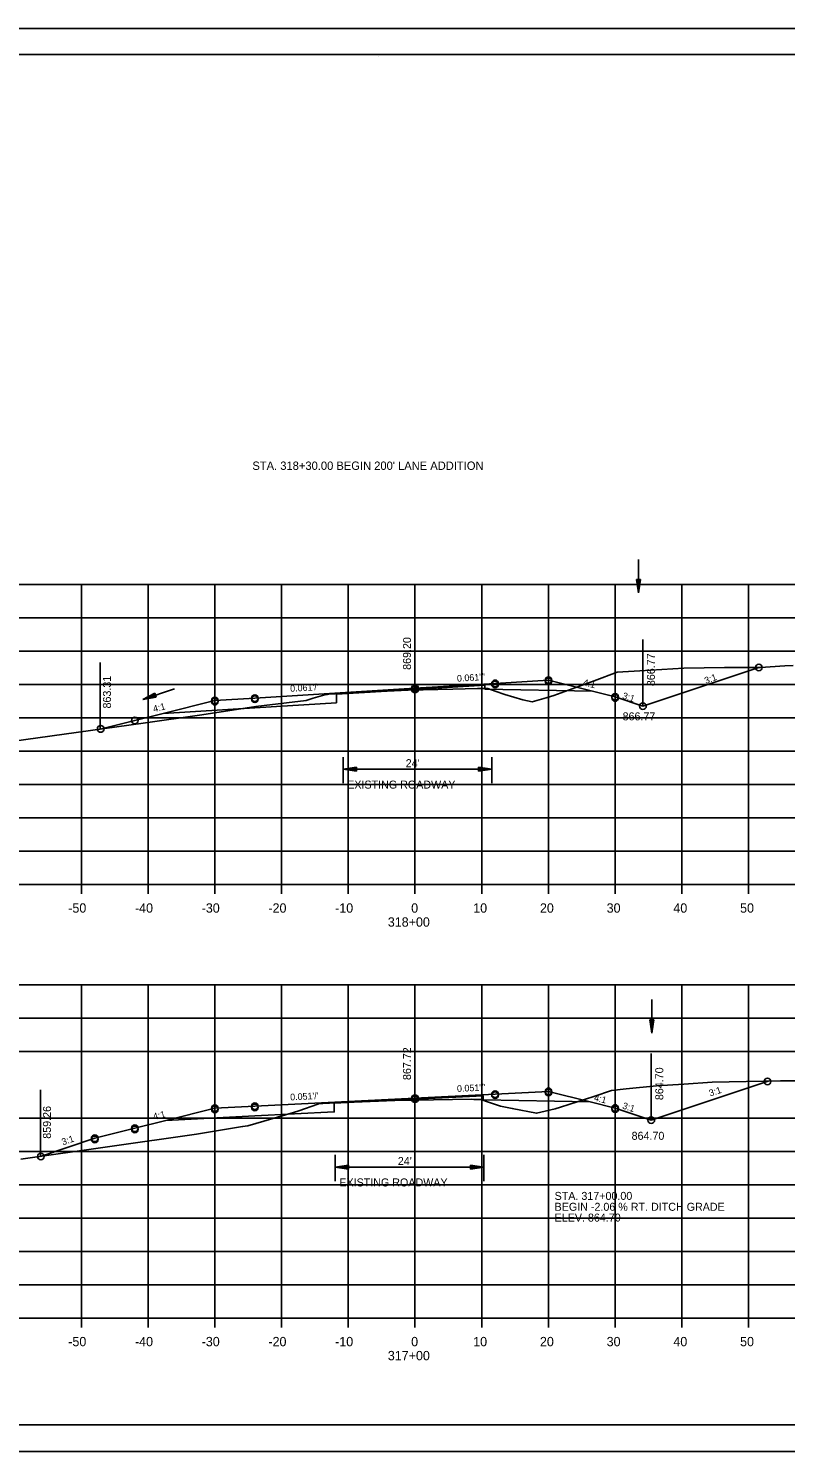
# Model space of a CAD drawing. Extents: x 1486524 to 1499135, y 326561 to 337924.
# Drawn here: x 1488925 to 1489038.4, y 335979.4 to 336192.7 of the extents above; entities that cross this region are included whole.
import ezdxf

# ---------------------------------------------------------------- set-up
doc = ezdxf.new("R2010")
doc.units = 0
for name, color, linetype in [('Default', 7, 'Continuous'), ('E_Const Align', 7, 'Continuous'), ('E_Const Align Station', 7, 'Continuous'), ('E_Ownership Information', 7, 'Continuous'), ('E_Property Line', 7, 'Continuous'), ('E_Proposed ROW and Easements', 7, 'Continuous'), ('E_Proposed ROW Fig Annot', 7, 'Continuous'), ('E_Quarter Calls', 7, 'Continuous'), ('E_Survey Point', 7, 'Continuous'), ('E_Title Sheet', 7, 'Continuous'), ('E_Tract Number', 7, 'Continuous'), ('R_Water Annot', 7, 'Continuous'), ('R_Xsect Elev', 7, 'Continuous'), ('R_Xsect Slope', 7, 'Continuous')]:
    doc.layers.add(name, color=color, linetype=linetype)

msp = doc.modelspace()

# ---------------------------------------------------------------- linework, layer by layer
at = {"layer": 'E_Const Align'}
for p, q in [((1488842.89, 336064.36), (1489122.89, 336064.36)), ((1488932.89, 336062.96), (1488932.89, 336064.36)), ((1488942.89, 336062.96), (1488942.89, 336064.36)), ((1488952.89, 336062.96), (1488952.89, 336064.36)), ((1488962.89, 336062.96), (1488962.89, 336064.36)), ((1488972.89, 336062.96), (1488972.89, 336064.36)), ((1488982.89, 336062.96), (1488982.89, 336064.36)), ((1488992.89, 336062.96), (1488992.89, 336064.36)), ((1489002.89, 336062.96), (1489002.89, 336064.36)), ((1489012.89, 336062.96), (1489012.89, 336064.36)), ((1489022.89, 336062.96), (1489022.89, 336064.36)), ((1489032.89, 336062.96), (1489032.89, 336064.36)), ((1488842.89, 335999.36), (1489122.89, 335999.36)), ((1488932.89, 335997.96), (1488932.89, 335999.36)), ((1488942.89, 335997.96), (1488942.89, 335999.36)), ((1488952.89, 335997.96), (1488952.89, 335999.36)), ((1488962.89, 335997.96), (1488962.89, 335999.36)), ((1488972.89, 335997.96), (1488972.89, 335999.36)), ((1488982.89, 335997.96), (1488982.89, 335999.36)), ((1488992.89, 335997.96), (1488992.89, 335999.36)), ((1489002.89, 335997.96), (1489002.89, 335999.36)), ((1489012.89, 335997.96), (1489012.89, 335999.36)), ((1489022.89, 335997.96), (1489022.89, 335999.36)), ((1489032.89, 335997.96), (1489032.89, 335999.36))]:
    msp.add_line(p, q, dxfattribs=at)
at = {"layer": 'E_Ownership Information'}
for p, q in [((1488842.89, 336109.36), (1489122.89, 336109.36)), ((1488932.89, 336064.36), (1488932.89, 336109.36)), ((1488942.89, 336064.36), (1488942.89, 336109.36)), ((1488952.89, 336064.36), (1488952.89, 336109.36)), ((1488962.89, 336064.36), (1488962.89, 336109.36)), ((1488972.89, 336064.36), (1488972.89, 336109.36)), ((1488982.89, 336064.36), (1488982.89, 336109.36)), ((1488992.89, 336064.36), (1488992.89, 336109.36)), ((1489002.89, 336064.36), (1489002.89, 336109.36)), ((1489012.89, 336064.36), (1489012.89, 336109.36)), ((1489022.89, 336064.36), (1489022.89, 336109.36)), ((1489032.89, 336064.36), (1489032.89, 336109.36)), ((1488842.89, 336104.36), (1489122.89, 336104.36)), ((1488842.89, 336099.36), (1489122.89, 336099.36)), ((1488842.89, 336094.36), (1489122.89, 336094.36)), ((1488842.89, 336089.36), (1489122.89, 336089.36)), ((1488842.89, 336084.36), (1489122.89, 336084.36)), ((1488842.89, 336079.36), (1489122.89, 336079.36)), ((1488842.89, 336074.36), (1489122.89, 336074.36)), ((1488842.89, 336069.36), (1489122.89, 336069.36)), ((1488842.89, 336064.36), (1489122.89, 336064.36)), ((1488842.89, 336049.36), (1489122.89, 336049.36)), ((1488932.89, 335999.36), (1488932.89, 336049.36)), ((1488942.89, 335999.36), (1488942.89, 336049.36)), ((1488952.89, 335999.36), (1488952.89, 336049.36)), ((1488962.89, 335999.36), (1488962.89, 336049.36)), ((1488972.89, 335999.36), (1488972.89, 336049.36)), ((1488982.89, 335999.36), (1488982.89, 336049.36)), ((1488992.89, 335999.36), (1488992.89, 336049.36)), ((1489002.89, 335999.36), (1489002.89, 336049.36)), ((1489012.89, 335999.36), (1489012.89, 336049.36)), ((1489022.89, 335999.36), (1489022.89, 336049.36)), ((1489032.89, 335999.36), (1489032.89, 336049.36)), ((1488842.89, 336044.36), (1489122.89, 336044.36)), ((1488842.89, 336039.36), (1489122.89, 336039.36)), ((1488842.89, 336029.36), (1489122.89, 336029.36)), ((1488842.89, 336024.36), (1489122.89, 336024.36)), ((1488842.89, 336019.36), (1489122.89, 336019.36)), ((1488842.89, 336014.36), (1489122.89, 336014.36)), ((1488842.89, 336009.36), (1489122.89, 336009.36)), ((1488842.89, 336004.36), (1489122.89, 336004.36)), ((1488842.89, 335999.36), (1489122.89, 335999.36))]:
    msp.add_line(p, q, dxfattribs=at)
at = {"layer": 'E_Property Line'}
for p, q in [((1488824.89, 336188.82), (1489141.07, 336188.82)), ((1488977.41, 336188.56), (1488977.41, 336188.56)), ((1488977.41, 336188.56), (1488977.41, 336188.56)), ((1489141.07, 335983.36), (1488824.89, 335983.36))]:
    msp.add_line(p, q, dxfattribs=at)
at = {"layer": 'E_Proposed ROW and Easements'}
for p, q in [((1488972.12, 336083.48), (1488972.12, 336079.55)), ((1488994.39, 336083.48), (1488994.39, 336079.55)), ((1488974.12, 336081.96), (1488972.12, 336081.66)), ((1488974.12, 336081.36), (1488972.12, 336081.66)), ((1488974.12, 336081.91), (1488972.45, 336081.66)), ((1488974.12, 336081.41), (1488972.45, 336081.66)), ((1488974.12, 336081.86), (1488972.79, 336081.66)), ((1488974.12, 336081.46), (1488972.79, 336081.66)), ((1488974.12, 336081.81), (1488973.13, 336081.66)), ((1488974.12, 336081.51), (1488973.13, 336081.66)), ((1488974.12, 336081.76), (1488973.47, 336081.66)), ((1488974.12, 336081.56), (1488973.47, 336081.66)), ((1488974.12, 336081.71), (1488973.8, 336081.66)), ((1488974.12, 336081.61), (1488973.8, 336081.66)), ((1488974.12, 336081.36), (1488974.12, 336081.96)), ((1488992.39, 336081.96), (1488994.39, 336081.66)), ((1488992.39, 336081.96), (1488992.39, 336081.36)), ((1488992.39, 336081.91), (1488994.06, 336081.66)), ((1488992.39, 336081.86), (1488993.71, 336081.66)), ((1488992.39, 336081.81), (1488993.38, 336081.66)), ((1488992.39, 336081.76), (1488993.04, 336081.66)), ((1488992.39, 336081.71), (1488992.71, 336081.66)), ((1488992.39, 336081.36), (1488994.39, 336081.66)), ((1488992.39, 336081.57), (1488993.04, 336081.66)), ((1488992.39, 336081.47), (1488993.71, 336081.66)), ((1488992.39, 336081.41), (1488994.06, 336081.66)), ((1488992.39, 336081.52), (1488993.38, 336081.66)), ((1488992.39, 336081.62), (1488992.71, 336081.66)), ((1488970.93, 336023.84), (1488970.93, 336019.91)), ((1488993.21, 336023.84), (1488993.21, 336019.91)), ((1488972.93, 336022.32), (1488970.93, 336022.02)), ((1488972.93, 336021.72), (1488970.93, 336022.02)), ((1488972.93, 336022.27), (1488971.27, 336022.02)), ((1488972.93, 336021.77), (1488971.27, 336022.02)), ((1488972.93, 336022.22), (1488971.61, 336022.02)), ((1488972.93, 336021.82), (1488971.61, 336022.02)), ((1488972.93, 336022.17), (1488971.95, 336022.02)), ((1488972.93, 336021.87), (1488971.95, 336022.02)), ((1488972.93, 336022.12), (1488972.28, 336022.02)), ((1488972.93, 336021.92), (1488972.28, 336022.02)), ((1488972.93, 336022.07), (1488972.62, 336022.02)), ((1488972.93, 336021.97), (1488972.62, 336022.02)), ((1488972.93, 336021.72), (1488972.93, 336022.32)), ((1488991.21, 336022.33), (1488993.21, 336022.03)), ((1488991.21, 336022.33), (1488991.21, 336021.73)), ((1488991.21, 336022.28), (1488992.88, 336022.03)), ((1488991.21, 336022.22), (1488992.53, 336022.03)), ((1488991.21, 336022.17), (1488992.2, 336022.03)), ((1488991.21, 336022.12), (1488991.86, 336022.03)), ((1488991.21, 336022.07), (1488991.53, 336022.03)), ((1488991.21, 336021.73), (1488993.21, 336022.03)), ((1488991.21, 336021.93), (1488991.86, 336022.03)), ((1488991.21, 336021.83), (1488992.53, 336022.03)), ((1488991.21, 336021.78), (1488992.88, 336022.03)), ((1488991.21, 336021.88), (1488992.2, 336022.03)), ((1488991.21, 336021.98), (1488991.53, 336022.03))]:
    msp.add_line(p, q, dxfattribs=at)
at = {"layer": 'E_Proposed ROW Fig Annot'}
for p, q in [((1489016.1, 336110.12), (1489016.4, 336108.12)), ((1489016.7, 336110.12), (1489016.1, 336110.12)), ((1489016.15, 336110.12), (1489016.4, 336108.46)), ((1489016.2, 336110.12), (1489016.4, 336108.8)), ((1489016.25, 336110.12), (1489016.4, 336109.13)), ((1489016.3, 336110.12), (1489016.4, 336109.47)), ((1489016.35, 336110.12), (1489016.4, 336109.81)), ((1489016.7, 336110.12), (1489016.4, 336108.12)), ((1489016.5, 336110.12), (1489016.4, 336109.47)), ((1489016.6, 336110.12), (1489016.4, 336108.8)), ((1489016.65, 336110.12), (1489016.4, 336108.46)), ((1489016.55, 336110.12), (1489016.4, 336109.13)), ((1489016.45, 336110.12), (1489016.4, 336109.81)), ((1488943.9, 336093.05), (1488942.1, 336092.12)), ((1488943.91, 336093), (1488942.41, 336092.23)), ((1488944.09, 336092.48), (1488943.9, 336093.05)), ((1488944.09, 336092.48), (1488942.1, 336092.12)), ((1488944.07, 336092.53), (1488942.41, 336092.23)), ((1488943.93, 336092.95), (1488942.74, 336092.34)), ((1488944.06, 336092.58), (1488942.74, 336092.34)), ((1488943.95, 336092.91), (1488943.06, 336092.45)), ((1488944.04, 336092.62), (1488943.06, 336092.45)), ((1488943.96, 336092.86), (1488943.38, 336092.56)), ((1488944.02, 336092.67), (1488943.38, 336092.56)), ((1488943.98, 336092.81), (1488943.69, 336092.66)), ((1488944.01, 336092.72), (1488943.69, 336092.66)), ((1488972.12, 336081.66), (1488994.39, 336081.66)), ((1489018.09, 336044.12), (1489018.39, 336042.12)), ((1489018.69, 336044.12), (1489018.09, 336044.12)), ((1489018.14, 336044.12), (1489018.39, 336042.45)), ((1489018.19, 336044.12), (1489018.39, 336042.8)), ((1489018.24, 336044.12), (1489018.39, 336043.13)), ((1489018.29, 336044.12), (1489018.39, 336043.47)), ((1489018.34, 336044.12), (1489018.39, 336043.8)), ((1489018.69, 336044.12), (1489018.39, 336042.12)), ((1489018.49, 336044.12), (1489018.39, 336043.47)), ((1489018.59, 336044.12), (1489018.39, 336042.8)), ((1489018.64, 336044.12), (1489018.39, 336042.45)), ((1489018.54, 336044.12), (1489018.39, 336043.13)), ((1489018.44, 336044.12), (1489018.39, 336043.8)), ((1488970.93, 336022.02), (1488993.21, 336022.03))]:
    msp.add_line(p, q, dxfattribs=at)
at = {"layer": 'E_Quarter Calls'}
for p, q in [((1488812.48, 336192.71), (1489145.82, 336192.71)), ((1488812.48, 335979.38), (1489145.82, 335979.38))]:
    msp.add_line(p, q, dxfattribs=at)
for points in [[(1488812.48, 336192.71), (1489145.82, 336192.71), (1489145.82, 335979.38), (1488812.48, 335979.38)], [(1489058.81, 336188.82), (1489058.81, 336178.94), (1489094.54, 336178.94), (1489094.54, 336176.02), (1489117.74, 336176.02), (1489117.74, 336151.69), (1489141.07, 336151.69), (1489141.07, 335983.36), (1488824.89, 335983.36), (1488824.89, 336188.82)]]:
    msp.add_lwpolyline(points, close=True, dxfattribs=at)
for centre in [(1489034.44, 336096.92), (1489034.44, 336096.92), (1489002.89, 336095.02), (1489002.89, 336095.02), (1489002.89, 336094.85), (1488982.89, 336093.8), (1488982.89, 336093.8), (1488982.89, 336093.63), (1488994.89, 336094.53), (1488994.89, 336094.53), (1488994.89, 336094.36), (1489012.89, 336092.52), (1489012.89, 336092.52), (1488952.89, 336091.97), (1488952.89, 336091.97), (1488952.89, 336091.8), (1488958.89, 336092.33), (1488958.89, 336092.33), (1488958.89, 336092.16), (1489012.89, 336092.35), (1489017.06, 336091.12), (1489017.06, 336091.12), (1488940.89, 336088.97), (1488940.89, 336088.97), (1488935.78, 336087.7), (1489035.72, 336034.86), (1488994.89, 336032.96), (1488994.89, 336032.96), (1488994.89, 336032.79), (1489002.89, 336033.37), (1489002.89, 336033.37), (1489002.89, 336033.2), (1488952.89, 336030.84), (1488952.89, 336030.84), (1488952.89, 336030.67), (1488958.89, 336031.14), (1488958.89, 336031.14), (1488958.89, 336030.97), (1488982.89, 336032.36), (1488982.89, 336032.36), (1488982.89, 336032.19), (1489012.89, 336030.87), (1489012.89, 336030.87), (1489012.89, 336030.7), (1489018.31, 336029.06), (1488934.89, 336026.34), (1488934.89, 336026.34), (1488940.89, 336027.84), (1488940.89, 336027.84), (1488940.89, 336027.67), (1488934.89, 336026.17), (1488926.82, 336023.6)]:
    msp.add_circle(centre, 0.5, dxfattribs=at)
at = {"layer": 'E_Survey Point'}
for points in [[(1488945.16, 336090.04), (1488958.89, 336090.87), (1488971.11, 336091.62), (1488971.11, 336092.91), (1488982.89, 336093.63), (1488993.36, 336094.27), (1488993.37, 336093.69), (1489009.5, 336093.36)], [(1488945.56, 336029.01), (1488958.89, 336029.68), (1488970.78, 336030.29), (1488970.78, 336031.58), (1488982.89, 336032.19), (1488993.09, 336032.71), (1488993.1, 336032.12), (1489009.15, 336031.8)]]:
    msp.add_lwpolyline(points, dxfattribs=at)
at = {"layer": 'E_Title Sheet'}
for points in [[(1488935.71, 336087.67), (1488940.89, 336088.97), (1488945.16, 336090.04), (1488952.89, 336091.97), (1488958.89, 336092.33), (1488982.89, 336093.8), (1488994.89, 336094.53), (1489002.89, 336095.02), (1489009.5, 336093.36), (1489012.89, 336092.52), (1489017.06, 336091.12), (1489034.44, 336096.92)], [(1488926.74, 336023.62), (1488934.89, 336026.34), (1488940.89, 336027.84), (1488945.56, 336029.01), (1488952.89, 336030.84), (1488958.89, 336031.14), (1488982.89, 336032.36), (1488994.89, 336032.96), (1489002.89, 336033.37), (1489009.15, 336031.8), (1489012.89, 336030.87), (1489018.31, 336029.06), (1489035.82, 336034.89)]]:
    msp.add_lwpolyline(points, dxfattribs=at)
at = {"layer": 'E_Tract Number'}
for points in [[(1488922.43, 336085.81), (1488942.17, 336088.58), (1488950.59, 336089.76), (1488951.6, 336089.92), (1488959.05, 336091.09), (1488963.63, 336091.62), (1488966.56, 336091.95), (1488967.65, 336092.3), (1488969.37, 336092.83), (1488969.77, 336092.88), (1488969.98, 336092.9), (1488977.65, 336093.33), (1488981.89, 336093.54), (1488988.56, 336093.68), (1488992.24, 336093.77), (1488993.26, 336093.77), (1488993.83, 336093.76), (1488994.91, 336093.37), (1488996.35, 336092.88), (1488999.08, 336092.08), (1489000.48, 336091.77), (1489002.56, 336092.36), (1489003.72, 336092.72), (1489009.75, 336094.94), (1489013.2, 336096.19), (1489016.61, 336096.41), (1489023.21, 336096.83), (1489029.28, 336096.91), (1489034.67, 336096.91), (1489038.34, 336097.15), (1489039.59, 336097.22)], [(1488923.83, 336023.21), (1488950.14, 336026.98), (1488957.04, 336028.08), (1488957.86, 336028.22), (1488964.66, 336030.21), (1488965.47, 336030.43), (1488968.32, 336031.45), (1488968.53, 336031.53), (1488969.06, 336031.57), (1488969.1, 336031.57), (1488970.1, 336031.61), (1488981.07, 336032.05), (1488982.78, 336032.07), (1488991.42, 336032.19), (1488991.71, 336032.17), (1488992.88, 336032.13), (1488993.45, 336031.92), (1488995.72, 336031.14), (1488997.48, 336030.82), (1489001.11, 336030.1), (1489003.89, 336030.73), (1489004.7, 336031.02), (1489009.72, 336032.6), (1489012.37, 336033.52), (1489014.53, 336033.73), (1489019.07, 336034.18), (1489023.19, 336034.44), (1489027.45, 336034.75), (1489037.68, 336034.93), (1489046.41, 336034.97)]]:
    msp.add_lwpolyline(points, dxfattribs=at)
at = {"layer": 'R_Water Annot'}
for p, q in [((1489016.4, 336108.12), (1489016.4, 336113.12)), ((1488942.1, 336092.12), (1488946.83, 336093.73)), ((1489018.39, 336042.12), (1489018.39, 336047.12))]:
    msp.add_line(p, q, dxfattribs=at)
at = {"layer": 'R_Xsect Elev'}
for p, q in [((1488982.89, 336093.56), (1488982.89, 336103.56)), ((1489017.06, 336091.12), (1489017.06, 336101.12)), ((1488935.71, 336087.67), (1488935.71, 336097.67)), ((1488982.89, 336032.07), (1488982.89, 336042.07)), ((1489018.31, 336029.06), (1489018.31, 336039.06)), ((1488926.74, 336023.62), (1488926.74, 336033.62))]:
    msp.add_line(p, q, dxfattribs=at)

# ---------------------------------------------------------------- texts
at = {"layer": 'Default'}
msp.add_text("STA. 318+30.00 BEGIN 200' LANE ADDITION", height=1.25, dxfattribs=at).set_placement((1488958.52, 336126.54))
at = {"layer": 'E_Const Align Station'}
for s, p in [('-50', (1488930.92, 336060.16)), ('-40', (1488940.92, 336060.16)), ('-30', (1488950.92, 336060.16)), ('-20', (1488960.92, 336060.16)), ('-10', (1488970.92, 336060.16)), ('0', (1488982.32, 336060.16)), ('10', (1488991.62, 336060.16)), ('20', (1489001.62, 336060.16)), ('30', (1489011.62, 336060.16)), ('40', (1489021.62, 336060.16)), ('50', (1489031.62, 336060.16)), ('318+00', (1488978.82, 336058.06)), ('-50', (1488930.92, 335995.16)), ('-40', (1488940.92, 335995.16)), ('-30', (1488950.92, 335995.16)), ('-20', (1488960.92, 335995.16)), ('-10', (1488970.92, 335995.16)), ('0', (1488982.32, 335995.16)), ('10', (1488991.62, 335995.16)), ('20', (1489001.62, 335995.16)), ('30', (1489011.62, 335995.16)), ('40', (1489021.62, 335995.16)), ('50', (1489031.62, 335995.16)), ('317+00', (1488978.82, 335993.06))]:
    msp.add_text(s, height=1.4, dxfattribs=at).set_placement(p)
at = {"layer": 'E_Proposed ROW Fig Annot'}
for s, p in [("24'", (1488981.5, 336081.97)), ('EXISTING ROADWAY', (1488972.73, 336078.76)), ("24'", (1488980.32, 336022.33)), ('EXISTING ROADWAY', (1488971.55, 336019.12)), ('STA. 317+00.00 ', (1489003.82, 336017.1)), ('BEGIN -2.06 % RT. DITCH GRADE', (1489003.82, 336015.47)), ('ELEV. 864.70', (1489003.82, 336013.85))]:
    msp.add_text(s, height=1.2, dxfattribs=at).set_placement(p)
at = {"layer": 'R_Xsect Elev'}
for s, p in [('869.20', (1488982.29, 336096.56)), ('866.77', (1489018.86, 336094.12)), ('863.31', (1488937.32, 336090.77)), ('867.72', (1488982.29, 336035.07)), ('864.70', (1489020.11, 336032.06)), ('859.26', (1488928.33, 336026.27))]:
    msp.add_text(s, height=1.2, rotation=90, dxfattribs=at).set_placement(p)
for s, p in [('866.77', (1489014.01, 336088.99)), ('864.70', (1489015.36, 336026.11))]:
    msp.add_text(s, height=1.2, dxfattribs=at).set_placement(p)
at = {"layer": 'R_Xsect Slope'}
for s, rotation, p in [("0.061'/'", 3.4907, (1488989.21, 336094.78)), ('4:1', 345.9638, (1489008.01, 336094.25)), ('3:1', 20.7679, (1489026.49, 336094.43)), ("0.061'/'", 3.4907, (1488964.21, 336093.26)), ('3:1', 341.5651, (1489013.88, 336092.29)), ('4:1', 14.0362, (1488943.76, 336090.2)), ("0.051'/'", 2.8956, (1488964.21, 336032.01)), ("0.051'/'", 2.8956, (1488989.21, 336033.28)), ('3:1', 18.0711, (1489027.15, 336032.59)), ('4:1', 345.9638, (1489009.66, 336031.99)), ('3:1', 341.5651, (1489013.89, 336030.82)), ('4:1', 14.0362, (1488943.76, 336029.07)), ('3:1', 18.4349, (1488930.12, 336025.28))]:
    msp.add_text(s, height=1, rotation=rotation, dxfattribs=at).set_placement(p)

doc.saveas('drawing.dxf')
